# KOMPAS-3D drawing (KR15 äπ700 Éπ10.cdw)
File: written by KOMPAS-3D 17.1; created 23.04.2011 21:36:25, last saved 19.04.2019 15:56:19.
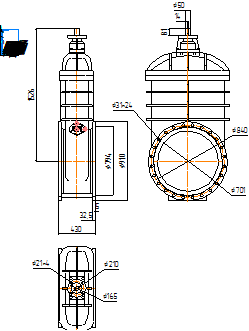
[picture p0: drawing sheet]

Sheet 1: A4, portrait

Title block, sheet 1: name: KR15 Ду700 Ру10; material: Внимание! Данный продукт является объектом авторского права ООО «Торговый Дом АДЛ». / Запрещается изменение, копирование, распространение / (в том числе путем копирования на другие сайты и ресурсы в Интернете) / или любое иное использование информации и объектов без предварительного / согласия правообладателя (ООО «Торговый Дом АДЛ»).; scale: 1:1; sheets: 1; organisation: ООО "Торговый дом АДЛ"; sheet format: A4; stored path: \\adlc.lan\data\АДЛ_ПКД\3D-модели\ADL production\Клиновые задвижки серии KR ГРАНАР\Клиновые задвижки KR15\С голым штоком\KOMPAS 2D\KR15 Ду700 Ру10.cdw

Views: Спереди 4, Проекционный вид 5
Dimensions and other numbers on the sheet: 910; 794; 1526; 430; 32,5; 5; 21; 210; 165; 1:1; 1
